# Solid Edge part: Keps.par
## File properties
Author: Türk
Template: Iso Part.par
Last saved by: Türk
Revision: 6
Application: Solid Edge
Accuracy: 0,990
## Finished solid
Body 1: solid body, 47 faces, 123 edges, 76 vertices.
  Faces by surface: plane 20, torus 15, cylinder 12
  Edges by curve: line 44, intersection 40, circle 39
Bounding box of the edges (mm; curved faces can reach further): 185.000 x 28.000 x 40.000, from (-20, -14, -20) to (165, 14, 20).
Cylindrical faces by radius (mm): R2.5 x8, R10 x1, R15 x2, R20 x1
Toroidal faces (ring radius, tube radius in mm): R10.5 r0.5 x2, R14.5 r0.5 x2, R15.5 r0.5 x1, R19.5 r0.5 x2, R24.6825 r20 x4, R34.7564 r20 x4
Planar faces by outward normal: +x 2, +y 5, +z 3, -x 2, -y 5, -z 3
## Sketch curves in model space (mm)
arc centre (97.5, 0, 2.5) radius 2.5 from (97.5, 0, 5) through (99.3184, 0, 4.2156) to (100, 0, 2.5)
line (100, 0, 2.5) -> (100, 0, -2.5)
arc centre (97.5, 0, -2.5) radius 2.5 from (97.5, 0, -5) through (99.3184, 0, -4.2156) to (100, 0, -2.5)
arc centre (22.5, 0, 2.5) radius 2.5 from (22.5, 0, 5) through (20.6816, 0, 4.2156) to (20, 0, 2.5)
line (20, 0, 2.5) -> (20, 0, -2.5)
arc centre (22.5, 0, -2.5) radius 2.5 from (22.5, 0, -5) through (20.6816, 0, -4.2156) to (20, 0, -2.5)
line (22.5, 0, -5) -> (97.5, 0, -5)
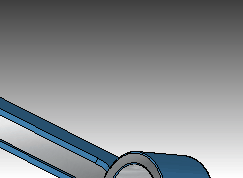
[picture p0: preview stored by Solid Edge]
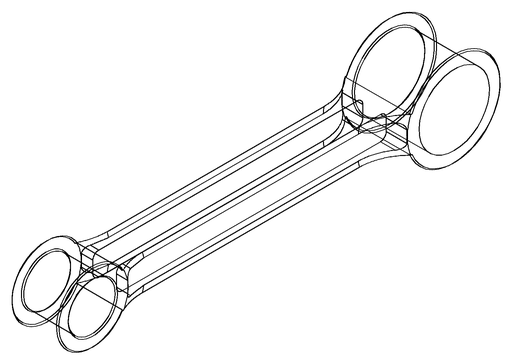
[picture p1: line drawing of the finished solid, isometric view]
